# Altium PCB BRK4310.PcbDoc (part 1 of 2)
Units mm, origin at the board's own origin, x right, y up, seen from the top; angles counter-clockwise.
Board outline 150 x 90 mm, 2 copper layers (Top Layer, Bottom Layer), stack 1.646 mm thick; 21 components, 213 nets, 662 pads, 124 vias.
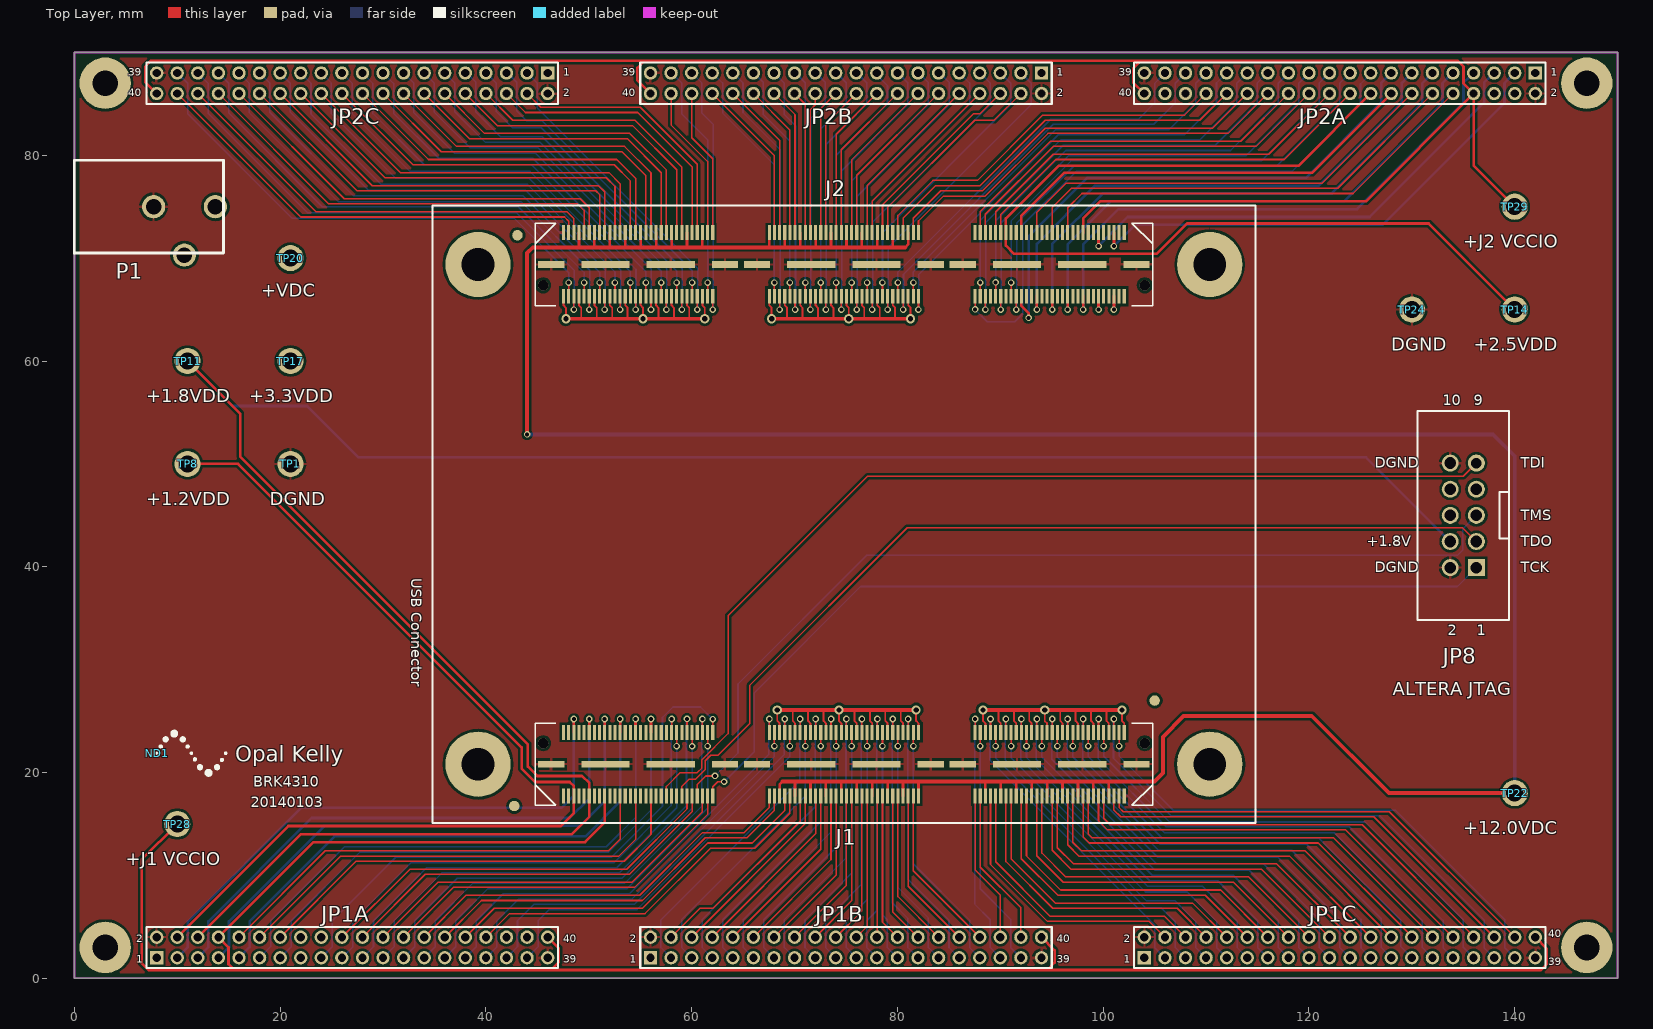
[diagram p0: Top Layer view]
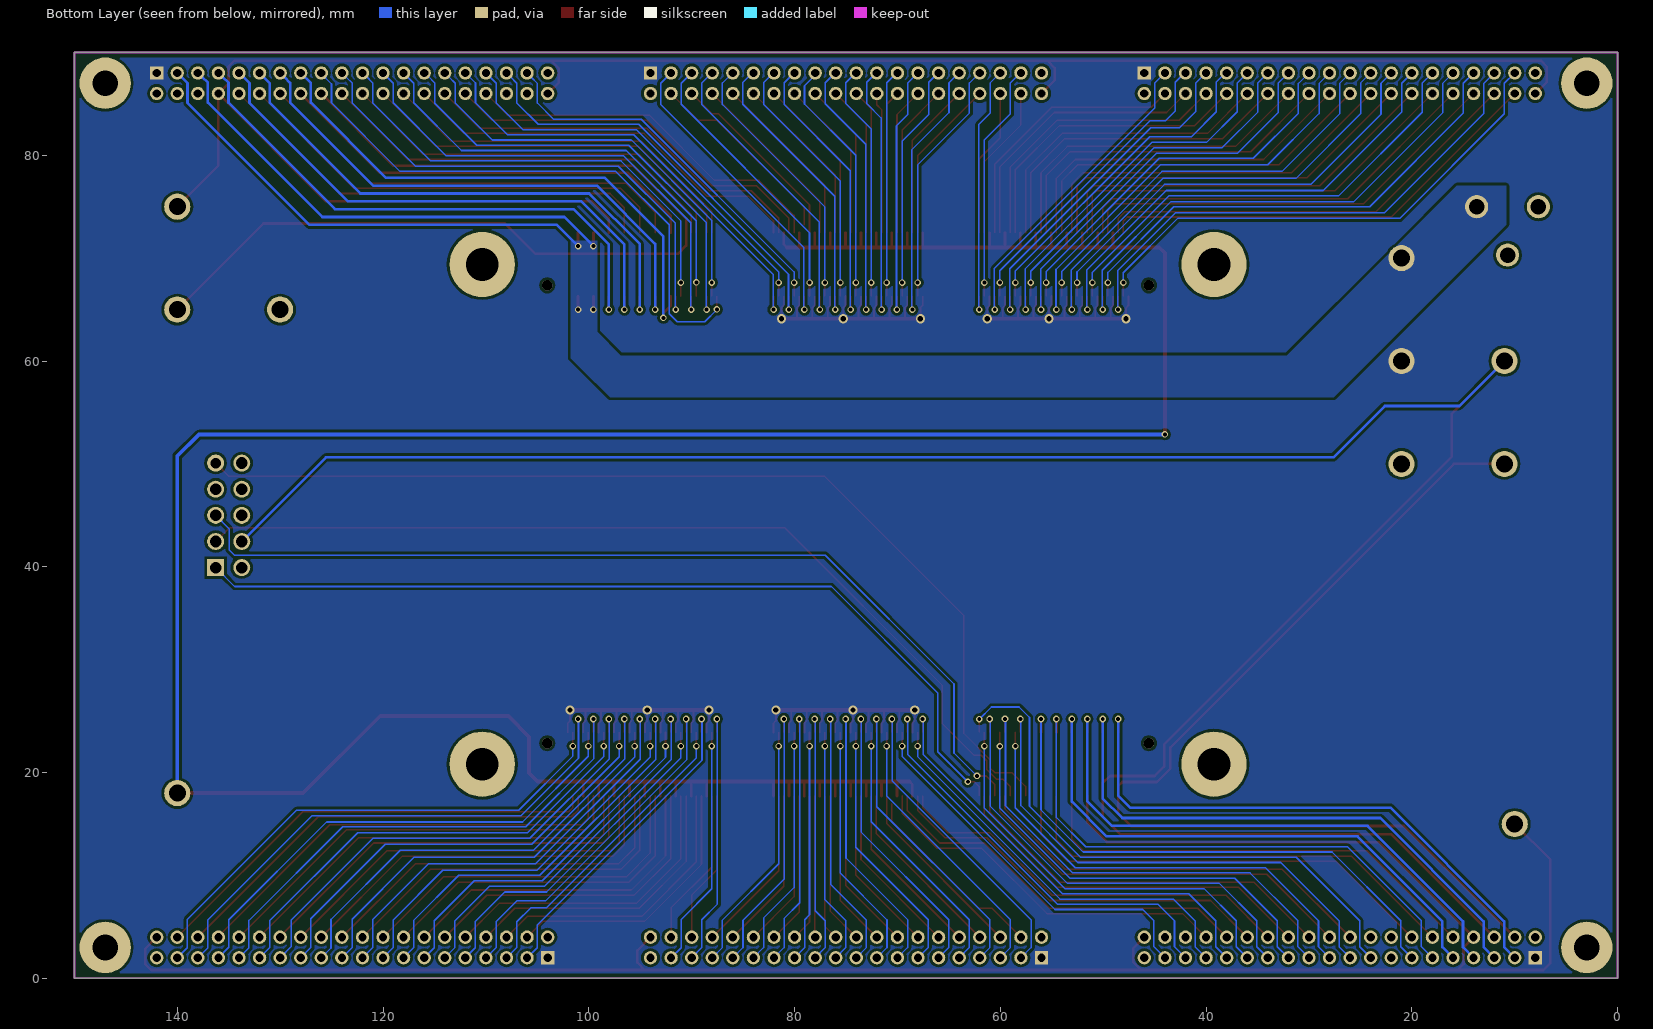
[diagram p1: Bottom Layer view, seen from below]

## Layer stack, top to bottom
Top Solder: solder mask 0.0102, Solder Resist, Dk 3.5
Top Layer: signal copper 0.0356
Dielectric1: core 1.5748, FR-4, Dk 4.8
Bottom Layer: signal copper 0.0356
Bottom Solder: solder mask 0.0102, Solder Resist, Dk 3.5

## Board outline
150,90 150,0 0,0 0,90

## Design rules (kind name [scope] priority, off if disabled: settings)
Clearance PolyClearance [InPolygon] p1: gap=0.254
Clearance [All] p2: gap=0.152
FabricationTestPointUsage TestPointUsage [All] p1: valid=0 allowmultiple=FALSE
FabricationTestpoint Testpoint [All] p1: side=3 testpointundercomponent=TRUE minsize=1.016 maxsize=2.54 preferedsize=1.524 minholesize=0 maxholesize=1.016 preferedholesize=0.813 testpointgrid=0.025 allowsidetop=TRUE allowsidebottom=TRUE usegrid=TRUE gridtolerance=0
HoleSize [All] p1: absolutevalues=TRUE maxlimit=6 minlimit=0.381 maxpercent=80.000 minpercent=20.000
PolygonConnect "Via Connect" [IsVia] p1: connectstyle=Direct reliefconductorwidth=0.254 reliefentries=4 polygonreliefangle="90 Angle" airgapwidth=0.254
PolygonConnect PolygonConnect_Top [OnLayer('Top Layer')] p2: connectstyle=Relief reliefconductorwidth=0.254 reliefentries=4 polygonreliefangle="90 Angle" airgapwidth=0.254
PolygonConnect PolygonConnect_Default [All] p3: connectstyle=Direct reliefconductorwidth=0.254 reliefentries=4 polygonreliefangle="90 Angle" airgapwidth=0.254
RoutingVias [All] p1: holewidth=0.381 width=0.635 viastyle="Through Hole" minholewidth=0.254 minwidth=0.508 maxholewidth=1.27 maxwidth=2.54
SilkToSolderMaskClearance SilkscreenOverComponentPads [IsPad] p1: minsilkscreentomaskgap=0.254 clearancetoexposedcopper=TRUE
SolderMaskExpansion [All] p1: expansion=0.102
Width [All] p1: maxlimit=1.016 minlimit=0.152 preferedwidth=0.152 minimp=50.000000 maximp=50.000000 favimp=50.000000
25 further rules are at their usual default settings.

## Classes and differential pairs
net class okPower: +1.2VDD +1.8VDD +2.5VDD +3.3VDD +12.0VDC +VCCIO2 +VCCIO3 +VCCIO4 +VCCIO5 +VCCIO6 +VDC +VREF_BANK2 +VREF_BANK3 +VREF_BANK4 +VREF_BANK5 +VREF_BANK6 +X_HSMC_VCCIO +Y_HSMC_VCCIO DGND
net class okJTAG: JTAG_TCK_1P8 JTAG_TDI_1P8 JTAG_TDO_1P8 JTAG_TMS_1P8

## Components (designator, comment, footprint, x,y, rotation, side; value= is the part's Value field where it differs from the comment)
J1 "QTH-090-01-F-D-A" QTH-090-01-X-D 74.795,20.815 r0 top locked
J2 "QTH-090-01-F-D-A" QTH-090-01-X-D 74.795,69.385 r180 top locked
JP1A "0877584016" HDR2X20-2MM 27,3 r0 top locked
JP1B "0877584016" HDR2X20-2MM 75,3 r0 top locked
JP1C "0877584016" HDR2X20-2MM 123,3 r0 top locked
JP2A "0877584016" HDR2X20-2MM 123,87 r180 top locked
JP2B "0877584016" HDR2X20-2MM 75,87 r180 top locked
JP2C "0877584016" HDR2X20-2MM 27,87 r180 top locked
JP8 "70246-1004" HDR2X5-SHRD 135,45 r90 top
ND1 "OKLOGO" oklogotiny 8.039,21.876 r0 top
P1 "PJ-102AH" CUI-PJ102A 0,75 r270 top
TP1 "DGND" TP_MED 21,50 r180 top
TP8 "+1.2VDD" TP_MED 11,50 r180 top
TP11 "+1.8VDD" TP_MED 11,60 r270 top
TP14 "+2.5VDD" TP_MED 140,65 r270 top
TP17 "+3.3VDD" TP_MED 21,60 r90 top
TP20 "+VDC" TP_MED 21,70 r180 top
TP22 "+12.0VDC" TP_MED 140,18 r270 top
TP24 "DGND" TP_MED 130,65 r270 top
TP28 "+J1 VCCIO" TP_MED 10,15 r270 top
TP29 "+J2 VCCIO" TP_MED 140,75 r270 top

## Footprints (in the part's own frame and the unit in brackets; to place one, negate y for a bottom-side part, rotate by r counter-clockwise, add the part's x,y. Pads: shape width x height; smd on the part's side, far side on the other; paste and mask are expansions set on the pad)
CUI-PJ102A [mm] "2.1mm/5.5mm DC power jack"
  round 2.25 hole 1.5: 1(0,13.7) 2(0,7.7) 3(4.7,10.7)
  silkscreen extent -4.5,0 4.5,14.5
HDR2X5-SHRD [mil] "0.1\" 2x5 shrouded header"
  rect 65x65 hole 44.88: 1(-200,-50)
  round 65 hole 44.88: 2(-200,50) 3(-100,-50) 4(-100,50) 5(0,-50) 6(0,50) 7(100,-50) 8(100,50) 10(200,50)
  round 65 hole 40: 9(200,-50)
  silkscreen extent -400,-175 400,175
HDR2X20-2MM [mm] "2mm 2x20 header"
  rect 1.3x1.3 hole 0.8: 1(-19,-1)
  round 1.3 hole 0.8: 2(-19,1) 3(-17,-1) 4(-17,1) 5(-15,-1) 6(-15,1) 7(-13,-1) 8(-13,1) 9(-11,-1) 10(-11,1) 11(-9,-1) 12(-9,1) 13(-7,-1) 14(-7,1) 15(-5,-1) 16(-5,1) 17(-3,-1) 18(-3,1) 19(-1,-1) 20(-1,1) 21(1,-1) 22(1,1) 23(3,-1) 24(3,1) 25(5,-1) 26(5,1) 27(7,-1) 28(7,1) 29(9,-1) 30(9,1) 31(11,-1) 32(11,1) 33(13,-1) 34(13,1) 35(15,-1) 36(15,1) 37(17,-1) 38(17,1) 39(19,-1) 40(19,1)
  silkscreen extent -20,-2 20,2
oklogotiny [mm] "Opal Kelly silkscreen logo (50 mil)."
  silkscreen extent -0.09,-2.1 6.75,2.1
QTH-090-01-X-D [mm]
  rect 2.54x0.64 smd: 0(-28.445,0) 0(-11.555,0) 0(-8.445,0) 0(8.445,0) 0(11.555,0) 0(28.445,0)
  rect 4.7x0.64 smd: 0(-23.175,0) 0(-16.825,0) 0(-3.175,0) 0(3.175,0) 0(16.825,0) 0(23.175,0)
  rect 0.3x1.45 smd: 1(-27.25,3.09) 2(-27.25,-3.09) 3(-26.75,3.09) 4(-26.75,-3.09) 5(-26.25,3.09) 6(-26.25,-3.09) 7(-25.75,3.09) 8(-25.75,-3.09) 9(-25.25,3.09) 10(-25.25,-3.09) 11(-24.75,3.09) 12(-24.75,-3.09) 13(-24.25,3.09) 14(-24.25,-3.09) 15(-23.75,3.09) 16(-23.75,-3.09) 17(-23.25,3.09) 18(-23.25,-3.09) 19(-22.75,3.09) 20(-22.75,-3.09) 21(-22.25,3.09) 22(-22.25,-3.09) 23(-21.75,3.09) 24(-21.75,-3.09) 25(-21.25,3.09) 26(-21.25,-3.09) 27(-20.75,3.09) 28(-20.75,-3.09) 29(-20.25,3.09) 30(-20.25,-3.09) 31(-19.75,3.09) 32(-19.75,-3.09) 33(-19.25,3.09) 34(-19.25,-3.09) 35(-18.75,3.09) 36(-18.75,-3.09) 37(-18.25,3.09) 38(-18.25,-3.09) 39(-17.75,3.09) 40(-17.75,-3.09) 41(-17.25,3.09) 42(-17.25,-3.09) 43(-16.75,3.09) 44(-16.75,-3.09) 45(-16.25,3.09) 46(-16.25,-3.09) 47(-15.75,3.09) 48(-15.75,-3.09) 49(-15.25,3.09) 50(-15.25,-3.09) 51(-14.75,3.09) 52(-14.75,-3.09) 53(-14.25,3.09) 54(-14.25,-3.09) 55(-13.75,3.09) 56(-13.75,-3.09) 57(-13.25,3.09) 58(-13.25,-3.09) 59(-12.75,3.09) 60(-12.75,-3.09) 61(-7.25,3.09) 62(-7.25,-3.09) 63(-6.75,3.09) 64(-6.75,-3.09) 65(-6.25,3.09) 66(-6.25,-3.09) 67(-5.75,3.09) 68(-5.75,-3.09) 69(-5.25,3.09) 70(-5.25,-3.09) 71(-4.75,3.09) 72(-4.75,-3.09) 73(-4.25,3.09) 74(-4.25,-3.09) 75(-3.75,3.09) 76(-3.75,-3.09) 77(-3.25,3.09) 78(-3.25,-3.09) 79(-2.75,3.09) 80(-2.75,-3.09) 81(-2.25,3.09) 82(-2.25,-3.09) 83(-1.75,3.09) 84(-1.75,-3.09) 85(-1.25,3.09) 86(-1.25,-3.09) 87(-0.75,3.09) 88(-0.75,-3.09) 89(-0.25,3.09) 90(-0.25,-3.09) 91(0.25,3.09) 92(0.25,-3.09) 93(0.75,3.09) 94(0.75,-3.09) 95(1.25,3.09) 96(1.25,-3.09) 97(1.75,3.09) 98(1.75,-3.09) 99(2.25,3.09) 100(2.25,-3.09) 101(2.75,3.09) 102(2.75,-3.09) 103(3.25,3.09) 104(3.25,-3.09) 105(3.75,3.09) 106(3.75,-3.09) 107(4.25,3.09) 108(4.25,-3.09) 109(4.75,3.09) 110(4.75,-3.09) 111(5.25,3.09) 112(5.25,-3.09) 113(5.75,3.09) 114(5.75,-3.09) 115(6.25,3.09) 116(6.25,-3.09) 117(6.75,3.09) 118(6.75,-3.09) 119(7.25,3.09) 120(7.25,-3.09) 121(12.75,3.09) 122(12.75,-3.09) 123(13.25,3.09) 124(13.25,-3.09) 125(13.75,3.09) 126(13.75,-3.09) 127(14.25,3.09) 128(14.25,-3.09) 129(14.75,3.09) 130(14.75,-3.09) 131(15.25,3.09) 132(15.25,-3.09) 133(15.75,3.09) 134(15.75,-3.09) 135(16.25,3.09) 136(16.25,-3.09) 137(16.75,3.09) 138(16.75,-3.09) 139(17.25,3.09) 140(17.25,-3.09) 141(17.75,3.09) 142(17.75,-3.09) 143(18.25,3.09) 144(18.25,-3.09) 145(18.75,3.09) 146(18.75,-3.09) 147(19.25,3.09) 148(19.25,-3.09) 149(19.75,3.09) 150(19.75,-3.09) 151(20.25,3.09) 152(20.25,-3.09) 153(20.75,3.09) 154(20.75,-3.09) 155(21.25,3.09) 156(21.25,-3.09) 157(21.75,3.09) 158(21.75,-3.09) 159(22.25,3.09) 160(22.25,-3.09) 161(22.75,3.09) 162(22.75,-3.09) 163(23.25,3.09) 164(23.25,-3.09) 165(23.75,3.09) 166(23.75,-3.09) 167(24.25,3.09) 168(24.25,-3.09) 169(24.75,3.09) 170(24.75,-3.09) 171(25.25,3.09) 172(25.25,-3.09) 173(25.75,3.09) 174(25.75,-3.09) 175(26.25,3.09) 176(26.25,-3.09) 177(26.75,3.09) 178(26.75,-3.09) 179(27.25,3.09) 180(27.25,-3.09)
  round 1.02 hole 1.02 unplated: MH(-29.24,2.03) MH(29.24,2.03)
  silkscreen extent -30,-4 30,4
TP_MED [mil] "Testpoint - medium sized"
  round 100 hole 65: 1(0,0)

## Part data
J1 J2: library part 000876, "0.5mm hi-speed, high-density header (Female)"
JP1A JP1B JP1C JP2A JP2B JP2C: library part 000583, "2mm header, 20x2, thru-hole"
JP8: library part 000777, "2.54mm, 10 Pos, Dual Row Header"
ND1: "Opal Kelly PCB Logo"
P1: library part 000356, "DC power connector - high current"
TP1 TP8 TP11 TP14 TP17 TP20 TP22 TP24 TP28 TP29: library part 000812, "Testpoint."

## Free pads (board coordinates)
  round 1.016 smd mask+0.508: FD2(43.066,72.22) FD2(105,27) FD3(42.75,16.75)
  round 5 hole 2.5: MH(3,3) MH(3,87) MH(147,3) MH(147,87)
  round 6.35 hole 3.175: MH2(39.235,69.385) MH3(39.235,20.815) MH4(110.355,69.385) MH5(110.355,20.815)

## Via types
v1: diameter 0.635, hole 0.381, Top Layer to Bottom Layer, tented both sides, 112 vias
v2: diameter 0.889, hole 0.508, Top Layer to Bottom Layer, tented both sides, 12 vias

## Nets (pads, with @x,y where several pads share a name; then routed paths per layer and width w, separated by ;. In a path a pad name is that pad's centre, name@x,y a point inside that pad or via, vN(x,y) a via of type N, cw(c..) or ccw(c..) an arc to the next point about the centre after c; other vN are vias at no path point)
+1.2VDD: J1.6 JP1A.4 TP8.1 | length 98
  Top Layer w0.254: JP1A.4@9.59,4.2 JP1A.4@9.695,4.305 ; JP1A.4@10,4 20.805,14.805 47.291,14.805 48.545,16.059 J1.6@48.545,17.725 48.545,18.684 48.146,19.083 44.793,19.083 43.472,20.404 43.472,22.436 15.908,50 TP8.1@11,50
+1.8VDD: J1.12 JP1A.6 JP8.4 TP11.1 | length 235.9
  Top Layer w0.254: TP11.1@11,60 16.129,54.871 16.129,50.694 44.082,22.741 44.082,20.582 44.996,19.667 49.34,19.667 50.045,18.962 J1.12@50.045,17.725 50.045,15.705 48.358,14.018 22.018,14.018 JP1A.6@12,4
  Bottom Layer w0.254: TP11.1@11,60 15.374,55.626 22.631,55.626 27.627,50.63 125.56,50.63 JP8.4@133.73,42.46
+2.5VDD: J2.48 JP2A.18 TP14.1 | length 97.6
  Top Layer w0.254: JP2A.18@126,86 118.976,78.976 95.669,78.976 90.545,73.852 J2.48@90.545,72.475 90.545,71.223 91.351,70.417 105.194,70.417 108.141,73.363 131.637,73.363 TP14.1@140,65
+3.3VDD: J1.65 J1.71 J1.77 J1.83 J1.89 J1.95 J1.101 J1.107 J1.113 J1.119 J1.125 J1.131 J1.137 J1.143 J1.149 J1.155 J1.161 J1.167 J1.173 J1.179 J2.65 J2.71 J2.77 J2.83 J2.89 J2.95 J2.101 J2.107 J2.113 J2.119 J2.125 J2.131 J2.137 J2.143 J2.149 J2.155 J2.161 J2.167 J2.173 J2.179 JP1A.1 JP1B.1 JP1C.1 JP2A.1 JP2B.1 JP2C.1 TP17.1 | length 145.3
  Top Layer w0.178: J2.179@47.545,66.295 47.545,65.401 47.772,65.173 v2(47.772,64.106) ; J2.173@49.045,66.295 49.045,65.401 49.272,65.173 49.272,64.106 ; J2.167@50.545,66.295 50.545,65.401 50.772,65.173 50.772,64.106 ; J2.161@52.045,66.295 52.045,65.401 52.272,65.173 52.272,64.106 ; J2.155@53.545,66.295 53.545,65.401 53.772,65.173 53.772,64.106 ; J2.149@55.038,66.316 55.038,65.422 55.266,65.194 v2@55.266,64.128 ; J2.143@56.545,66.295 56.545,65.401 56.772,65.173 56.772,64.106 ; J2.137@58.045,66.295 58.045,65.401 58.272,65.173 58.272,64.106 ; J2.131@59.545,66.295 59.545,65.401 59.772,65.173 59.772,64.106 ; J2.125@61.045,66.295 61.045,65.401 61.272,65.173 v2(61.272,64.106) ; J2.119@67.545,66.295 67.545,65.401 67.772,65.173 v2(67.772,64.106) ; v2(68.318,26.094) 68.318,25.027 68.545,24.799 J1.65@68.545,23.905 ; J2.113@69.045,66.295 69.045,65.401 69.272,65.173 69.272,64.106 ; 69.818,26.094 69.818,25.027 70.045,24.799 J1.71@70.045,23.905 ; J2.107@70.545,66.295 70.545,65.401 70.772,65.173 70.772,64.106 ; 71.318,26.094 71.318,25.027 71.545,24.799 J1.77@71.545,23.905 ; J2.101@72.045,66.295 72.045,65.401 72.272,65.173 72.272,64.106 ; 72.818,26.094 72.818,25.027 73.045,24.799 J1.83@73.045,23.905 ; J2.95@73.545,66.295 73.545,65.401 73.772,65.173 73.772,64.106 ; v2@74.324,26.072 74.324,25.006 74.552,24.778 J1.89@74.552,23.884 ; J2.89@75.038,66.316 75.038,65.422 75.266,65.194 v2@75.266,64.128 ; 75.818,26.094 75.818,25.027 76.045,24.799 J1.95@76.045,23.905 ; J2.83@76.545,66.295 76.545,65.401 76.772,65.173 76.772,64.106 ; 77.318,26.094 77.318,25.027 77.545,24.799 J1.101@77.545,23.905 ; J2.77@78.045,66.295 78.045,65.401 78.272,65.173 78.272,64.106 ; 78.818,26.094 78.818,25.027 79.045,24.799 J1.107@79.045,23.905 ; J2.71@79.545,66.295 79.545,65.401 79.772,65.173 79.772,64.106 ; 80.318,26.094 80.318,25.027 80.545,24.799 J1.113@80.545,23.905 ; J2.65@81.045,66.295 81.045,65.401 81.272,65.173 v2(81.272,64.106) ; v2(81.818,26.094) 81.818,25.027 82.045,24.799 J1.119@82.045,23.905 ; v2(88.318,26.094) 88.318,25.027 88.545,24.799 J1.125@88.545,23.905 ; 89.818,26.094 89.818,25.027 90.045,24.799 J1.131@90.045,23.905 ; 91.318,26.094 91.318,25.027 91.545,24.799 J1.137@91.545,23.905 ; 92.818,26.094 92.818,25.027 93.045,24.799 J1.143@93.045,23.905 ; v2@94.324,26.072 94.324,25.006 94.552,24.778 J1.149@94.552,23.884 ; 95.818,26.094 95.818,25.027 96.045,24.799 J1.155@96.045,23.905 ; 97.318,26.094 97.318,25.027 97.545,24.799 J1.161@97.545,23.905 ; 98.818,26.094 98.818,25.027 99.045,24.799 J1.167@99.045,23.905 ; 100.318,26.094 100.318,25.027 100.545,24.799 J1.173@100.545,23.905 ; v2(101.818,26.094) 101.818,25.027 102.045,24.799 J1.179@102.045,23.905
  Top Layer w0.381: v2(47.772,64.106) 49.272,64.106 50.772,64.106 52.272,64.106 53.772,64.106 56.772,64.106 58.272,64.106 59.772,64.106 v2(61.272,64.106) ; v2(67.772,64.106) 69.272,64.106 70.772,64.106 72.272,64.106 73.772,64.106 76.772,64.106 78.272,64.106 79.772,64.106 v2(81.272,64.106) ; v2(68.318,26.094) 69.818,26.094 71.318,26.094 72.818,26.094 75.818,26.094 77.318,26.094 78.818,26.094 80.318,26.094 v2(81.818,26.094) ; v2(88.318,26.094) 89.818,26.094 91.318,26.094 92.818,26.094 95.818,26.094 97.318,26.094 98.818,26.094 100.318,26.094 v2(101.818,26.094)
  other v2: 74.318,26.094 94.318,26.094 55.272,64.106 75.272,64.106
+12.0VDC: J1.66 J1.72 J1.78 J1.84 J1.90 J1.96 J1.102 J1.108 J1.114 J1.120 J1.126 J1.132 J1.138 J1.144 J1.150 J1.156 J1.162 J1.168 J1.174 J2.66 J2.72 J2.78 J2.84 J2.90 J2.96 J2.102 J2.108 J2.114 J2.120 J2.126 J2.132 J2.138 J2.144 J2.150 J2.156 J2.162 J2.168 J2.174 TP22.1 | length 317.5
  Top Layer w0.254: 49.045,71.092 J2.174@49.045,72.475 ; 50.545,71.091 J2.168@50.545,72.475 ; 52.045,71.064 J2.162@52.045,72.475 ; 53.545,71.063 J2.156@53.545,72.475 ; 55.045,71.067 J2.150@55.045,72.475 ; 56.545,71.085 J2.144@56.545,72.475 ; 58.045,71.059 J2.138@58.045,72.475 ; 59.545,71.057 J2.132@59.545,72.475 ; 61.045,71.056 J2.126@61.045,72.475 ; 67.545,71.058 J2.120@67.545,72.475 ; J1.66@68.545,17.725 68.545,18.863 68.83,19.148 ; 69.045,71.082 J2.114@69.045,72.475 ; J1.72@70.045,17.725 70.045,19.144 ; 70.545,71.055 J2.108@70.545,72.475 ; J1.78@71.545,17.725 71.545,19.126 ; 72.045,71.079 J2.102@72.045,72.475 ; J1.84@73.045,17.725 73.045,19.147 ; 73.545,71.078 J2.96@73.545,72.475 ; J1.90@74.545,17.725 74.545,19.098 ; 75.045,71.102 J2.90@75.045,72.475 ; J1.96@76.045,17.725 76.045,19.122 ; 76.545,71.053 J2.84@76.545,72.475 ; J1.102@77.545,17.725 77.545,19.121 ; 78.045,71.074 J2.78@78.045,72.475 ; J1.108@79.045,17.725 79.045,19.145 ; 79.545,71.056 J2.72@79.545,72.475 ; J1.114@80.545,17.725 80.545,19.118 ; 80.76,71.052 81.045,71.337 J2.66@81.045,72.475 ; J1.120@82.045,17.725 82.045,19.142 ; J1.126@88.545,17.725 88.545,19.144 ; J1.132@90.045,17.725 90.045,19.143 ; J1.138@91.545,17.725 91.545,19.141 ; J1.144@93.045,17.725 93.045,19.115 ; J1.150@94.545,17.725 94.545,19.133 ; J1.156@96.045,17.725 96.045,19.137 ; J1.162@97.545,17.725 97.545,19.136 ; J1.168@99.045,17.725 99.045,19.109 ; J1.174@100.545,17.725 100.545,19.108
  Top Layer w0.381: v1(44,52.871) 44,70.5 44.552,71.052 49.086,71.052 ; 49.045,71.092 49.086,71.052 ; 50.545,71.091 50.584,71.052 ; 53.545,71.063 53.556,71.052 ; 61.045,71.056 61.049,71.052 ; 67.545,71.058 67.552,71.052 ; 68.83,19.148 70.05,19.148 ; 69.045,71.082 69.076,71.052 ; 70.045,19.144 70.05,19.148 ; 70.545,71.055 70.549,71.052 ; 71.545,19.126 71.523,19.148 ; 72.045,71.079 72.073,71.052 ; 73.045,19.147 73.047,19.148 ; 74.545,19.098 74.495,19.148 ; 75.045,71.102 75.095,71.052 ; 76.545,71.053 76.543,71.052 ; 77.545,19.121 77.517,19.148 ; 78.045,71.074 78.067,71.052 ; 79.045,19.145 79.041,19.148 ; 79.545,71.056 79.54,71.052 ; 80.545,19.118 80.514,19.148 ; 80.76,71.052 79.54,71.052 ; 82.045,19.142 82.038,19.148 ; 88.545,19.144 88.541,19.148 ; 96.045,19.137 96.034,19.148 ; 99.045,19.109 99.006,19.148 ; 100.53,19.123 100.545,19.108 ; TP22.1@140,18 127.771,18 120.269,25.502 107.823,25.502 105.795,23.474 105.795,19.943 105,19.148 99.006,19.148 ; 49.086,71.052 50.584,71.052 ; 50.584,71.052 53.556,71.052 ; 53.556,71.052 61.049,71.052 ; 61.049,71.052 67.552,71.052 ; 67.552,71.052 69.076,71.052 ; 69.076,71.052 70.549,71.052 ; 70.05,19.148 71.523,19.148 ; 70.549,71.052 72.073,71.052 ; 71.523,19.148 73.047,19.148 ; 72.073,71.052 75.095,71.052 ; 73.047,19.148 74.495,19.148 ; 74.495,19.148 77.517,19.148 ; 75.095,71.052 76.543,71.052 ; 76.543,71.052 78.067,71.052 ; 77.517,19.148 79.041,19.148 ; 78.067,71.052 79.54,71.052 ; 79.041,19.148 80.514,19.148 ; 80.514,19.148 82.038,19.148 ; 82.038,19.148 88.541,19.148 ; 88.541,19.148 96.034,19.148 ; 96.034,19.148 99.006,19.148
  Bottom Layer w0.381: v1(44,52.871) 137.886,52.871 140,50.757 TP22.1@140,18
+VCCIO2: J1.5 JP1A.3 | length 55.3
  Top Layer w0.254: J1.5@48.545,23.905 v1(48.545,25.206)
  Bottom Layer w0.254: JP1A.3@10,2 11.031,3.031 11.031,5.545 22.08,16.594 47.384,16.594 48.545,17.755 v1(48.545,25.206)
+VCCIO3: J1.11 JP1A.5 | length 55
  Top Layer w0.254: J1.11@50.045,23.905 v1(50.045,25.206)
  Bottom Layer w0.254: JP1A.5@12,2 13.031,3.031 13.031,5.545 23.064,15.578 48.146,15.578 50.045,17.477 v1(50.045,25.206)
+VCCIO4: J2.17 JP2A.7 | length 53.6
  Top Layer w0.254: v1(98.045,64.994) J2.17@98.045,66.295
  Bottom Layer w0.254: v1(98.045,64.994) 98.045,71.319 101.486,74.76 124.664,74.76 135.014,85.11 135.014,87.054 135.59,87.63 JP2A.7@135.59,88.2
+VCCIO5: J2.23 JP2A.9 | length 53.2
  Top Layer w0.254: v1(96.545,64.994) J2.23@96.545,66.295
  Bottom Layer w0.254: v1(96.545,64.994) 96.545,71.343 100.724,75.522 123.426,75.522 132.982,85.078 132.982,87.028 133.59,87.636 JP2A.9@133.59,88.2
+VCCIO6: J2.29 JP2A.11 | length 52.6
  Top Layer w0.254: v1@95.045,65.017 J2.29@95.045,66.295
  Bottom Layer w0.254: v1(95.045,64.994) 95.045,71.367 99.962,76.284 122.197,76.284 131.001,85.088 131.001,86.977 131.59,87.567 JP2A.11@131.59,88.2
+VDC: J2.5 J2.6 J2.11 J2.12 JP2A.3 JP2A.5 P1.1 TP20.1 | length 98.8
  Top Layer w0.254: v1(99.545,64.994) J2.11@99.545,66.295 ; v1(99.545,71.174) J2.12@99.545,72.475 ; v1(101.045,64.994) J2.5@101.045,66.295 ; v1(101.045,71.174) J2.6@101.045,72.475
  Bottom Layer w0.254: v1(99.545,71.174) 102.369,73.998 125.902,73.998 137.021,85.117 137.021,87.054 137.59,87.623 JP2A.5@137.59,88.2 ; v1(101.045,71.174) 103.107,73.236 127.14,73.236 139.002,85.098 139.002,87.002 139.59,87.59 JP2A.3@139.59,88.2
+VREF_BANK2: J1.17 JP1A.7 | length 54.6
  Top Layer w0.254: J1.17@51.545,23.905 v1(51.545,25.206)
  Bottom Layer w0.254: JP1A.7@14,2 15.031,3.031 15.031,5.545 24.302,14.816 49.162,14.816 51.545,17.199 v1(51.545,25.206)
+VREF_BANK3: J1.23 JP1A.9 | length 54.1
  Top Layer w0.254: J1.23@53.045,23.905 v1(53.045,25.206)
  Bottom Layer w0.254: JP1A.9@16,2 17.031,3.031 17.031,5.545 25.286,13.8 49.67,13.8 53.045,17.175 v1(53.045,25.206)
+VREF_BANK4: J2.35 JP2A.13 | length 52.1
  Top Layer w0.254: v1@93.545,65.041 J2.35@93.545,66.295
  Bottom Layer w0.254: v1(93.545,64.994) 93.545,71.391 99.2,77.046 120.959,77.046 129.02,85.106 129.02,87.028 129.59,87.599 JP2A.13@129.59,88.2
+VREF_BANK5: J2.41 JP2A.15 | length 53.3
  Top Layer w0.254: J2.41@92.045,66.295 92.045,65.354 92.748,64.651 v1(92.748,64.194) v1@92.774,64.168
  Bottom Layer w0.254: v1(92.748,64.194) 92.748,72.118 98.438,77.808 119.698,77.808 127.013,85.123 127.013,87.013 JP2A.15@128,88
+VREF_BANK6: J2.42 JP2A.16 | length 42.5
  Top Layer w0.254: J2.42@92.045,72.475 92.045,74.133 96.203,78.291 120.291,78.291 JP2A.16@128,86
+X_HSMC_VCCIO: J1.18 JP1A.8 JP1A.40 JP1B.40 JP1C.40 TP28.1 | length 211.7
  Top Layer w0.254: TP28.1@10,15 6.541,11.541 6.541,1.481 7.209,0.813 15.545,0.813 ; JP1A.40@46,4 47.092,2.908 47.092,1.575 46.33,0.813 ; J1.18@51.545,17.725 51.545,15.122 49.653,13.23 23.23,13.23 JP1A.8@14,4 14.986,3.014 14.986,1.372 15.545,0.813 ; JP1B.40@94,4 95.275,2.725 95.275,1.524 94.564,0.813 ; JP1C.40@142,4 143.129,2.871 143.129,1.397 142.545,0.813 94.564,0.813 ; 15.545,0.813 46.33,0.813 ; 46.33,0.813 94.564,0.813
+Y_HSMC_VCCIO: J2.18 JP2A.8 JP2A.40 JP2B.40 JP2C.40 TP29.1 | length 199.7
  Top Layer w0.254: JP2C.40@8,86 6.871,87.129 6.871,88.603 7.455,89.187 55.436,89.187 ; JP2B.40@56,86 54.725,87.275 54.725,88.476 55.436,89.187 ; J2.18@98.045,72.475 98.045,73.859 99.708,75.522 125.522,75.522 JP2A.8@136,86 ; JP2A.40@104,86 102.908,87.092 102.908,88.425 103.67,89.187 ; TP29.1@140,75 136,79 JP2A.8@136,86 ; 55.436,89.187 103.67,89.187 ; 103.67,89.187 134.455,89.187 135.014,88.628 135.014,86.986 JP2A.8@136,86
BANK1_CLK: J1.29 JP1A.11 | length 54.5
  Top Layer w0.254: J1.29@54.545,23.905 v1@54.545,25.183
  Bottom Layer w0.152: JP1A.11@18,2 19.073,3.073 19.073,5.596 26.261,12.784 51.702,12.784 54.545,15.627 v1(54.545,25.206)
BANK8_CLK: J1.35 JP1A.13 | length 53.6
  Top Layer w0.254: J1.35@56.045,23.905 v1@56.045,25.159
  Bottom Layer w0.152: JP1A.13@20,2 21.073,3.073 21.073,5.596 27.753,12.276 51.956,12.276 56.045,16.365 v1(56.045,25.206)
C_DET: J2.59 JP2A.17 | length 56.5
  Top Layer w0.152: v1(87.545,65.01) J2.59@87.545,66.295
  Bottom Layer w0.152: v1(87.545,65.01) 88.728,63.827 91.411,63.827 92.19,64.606 92.19,73.242 97.38,78.432 118.345,78.432 125.006,85.093 125.006,86.927 125.59,87.51 JP2A.17@125.59,88.2
DGND: J1.0 J1.180 J2.0 J2.180 JP1A.2 JP1A.39 JP1B.2 JP1B.39 JP1C.2 JP1C.39 JP2A.2 JP2A.39 JP2B.2 JP2B.39 JP2C.2 JP2C.39 JP8.2 JP8.10 P1.2 TP1.1 TP24.1
J1_49: J1.49 JP1A.23 | length 46.8
  Top Layer w0.152: J1.49@59.545,23.905 v1(59.545,25.208)
  Bottom Layer w0.152: JP1A.23@30,2 31.073,3.073 31.073,5.596 35.721,10.244 52.972,10.244 59.499,16.771 v1@59.499,25.142
J1_50: J1.50 JP1A.20 | length 40
  Top Layer w0.152: JP1A.20@26,4 32.614,10.614 53.692,10.614 59.545,16.467 J1.50@59.545,17.725
J1_51: J1.51 JP1A.25 | length 42.9
  Top Layer w0.152: v1(60.045,22.555) J1.51@60.045,23.905
  Bottom Layer w0.152: JP1A.25@32,2 33.073,3.073 33.073,5.596 37.213,9.736 53.226,9.736 60.045,16.555 v1(60.045,22.555)
J1_52: J1.52 JP1A.22 | length 38.6
  Top Layer w0.152: JP1A.22@28,4 34.106,10.106 53.946,10.106 60.045,16.205 J1.52@60.045,17.725
J1_55: J1.55 JP1A.27 | length 44.3
  Top Layer w0.152: J1.55@61.045,23.905 v1(61.045,25.206)
  Bottom Layer w0.152: JP1A.27@34,2 35.073,3.073 35.073,5.596 38.705,9.228 53.48,9.228 60.999,16.747 v1@60.999,25.16
J1_56: J1.56 JP1A.24 | length 37.6
  Top Layer w0.152: JP1A.24@30,4 35.344,9.344 54.2,9.344 61.045,16.189 J1.56@61.045,17.725
J1_57: J1.57 JP1A.29 | length 40.4
  Top Layer w0.152: v1(61.545,22.573) J1.57@61.545,23.905
  Bottom Layer w0.152: JP1A.29@36,2 37.073,3.073 37.073,5.596 40.197,8.72 53.734,8.72 61.545,16.531 v1(61.545,22.573)
J1_58: J1.58 JP1A.26 | length 36.3
  Top Layer w0.152: JP1A.26@32,4 36.836,8.836 54.454,8.836 61.545,15.927 J1.58@61.545,17.725
J1_61: J1.61 JP1A.31 | length 43.9
  Top Layer w0.152: J1.61@67.545,23.905 v1(67.545,25.206)
  Bottom Layer w0.152: JP1A.31@38,2 39.073,3.073 39.073,5.596 41.689,8.212 53.95,8.212 67.499,21.761 v1@67.499,25.16
J1_62: J1.62 JP1A.28 | length 39.9
  Top Layer w0.152: JP1A.28@34,4 38.074,8.074 54.962,8.074 61.058,14.17 65.122,14.17 67.545,16.593 J1.62@67.545,17.725
J1_63: J1.63 JP1A.33 | length 40
  Top Layer w0.152: v1(68.045,22.573) J1.63@68.045,23.905
  Bottom Layer w0.152: JP1A.33@40,2 41.073,3.073 41.073,5.596 43.181,7.704 54.2,7.704 68.045,21.549 v1(68.045,22.573)
J1_64: J1.64 JP1A.30 | length 38.5
  Top Layer w0.152: JP1A.30@36,4 39.566,7.566 55.216,7.566 61.312,13.662 65.376,13.662 68.045,16.331 J1.64@68.045,17.725
J1_67: J1.67 JP1A.35 | length 41.4
  Top Layer w0.152: J1.67@69.045,23.905 v1(69.045,25.206)
  Bottom Layer w0.152: JP1A.35@42,2 43.073,3.073 43.073,5.596 44.673,7.196 54.434,7.196 68.999,21.761 v1@68.999,25.16
J1_68: J1.68 JP1A.32 | length 37.6
  Top Layer w0.152: JP1A.32@38,4 40.804,6.804 55.216,6.804 61.566,13.154 65.884,13.154 69.045,16.315 J1.68@69.045,17.725
J1_69: J1.69 JP1A.37 | length 37.5
  Top Layer w0.152: v1(69.545,22.573) J1.69@69.545,23.905
  Bottom Layer w0.152: JP1A.37@44,2 45.073,3.073 45.073,5.596 46.165,6.688 54.684,6.688 69.545,21.549 v1(69.545,22.573)
J1_70: J1.70 JP1A.34 | length 36.2
  Top Layer w0.152: JP1A.34@40,4 42.296,6.296 55.47,6.296 61.82,12.646 66.138,12.646 69.545,16.053 J1.70@69.545,17.725
J1_73: J1.73 JP1B.3 | length 30.5
  Top Layer w0.152: J1.73@70.545,23.905 v1(70.545,25.206)
  Bottom Layer w0.152: JP1B.3@58,2 57.015,2.985 57.015,5.697 70.499,19.182 v1@70.499,25.16
J1_74: J1.74 JP1B.4 | length 18.9
  Top Layer w0.152: JP1B.4@58,4 60.804,6.804 62.074,6.804 70.545,15.275 70.545,16.964
J1_75: J1.75 JP1B.5 | length 27.3
  Top Layer w0.152: v1(71.045,22.573) J1.75@71.045,23.905
  Bottom Layer w0.152: JP1B.5@60,2 59.015,2.985 59.015,5.697 71.045,17.728 v1(71.045,22.573)
J1_76: J1.76 JP1B.6 | length 18.3
  Top Layer w0.152: JP1B.6@60,4 71.013,15.013 71.045,15.013 J1.76@71.045,17.725
J1_79: J1.79 JP1B.7 | length 29.4
  Top Layer w0.152: J1.79@72.045,23.905 v1(72.045,25.206)
  Bottom Layer w0.152: JP1B.7@62,2 61.015,2.985 61.015,5.697 71.999,16.682 v1@71.999,25.16
J1_80: J1.80 JP1B.8 | length 17.9
  Top Layer w0.152: JP1B.8@62,4 72.045,14.045 J1.80@72.045,17.725
J1_81: J1.81 JP1B.9 | length 26.3
  Top Layer w0.152: v1(72.545,22.573) J1.81@72.545,23.905
  Bottom Layer w0.152: JP1B.9@64,2 63.015,2.985 63.015,5.697 72.545,15.228 v1(72.545,22.573)
J1_82: J1.82 JP1B.10 | length 17.3
  Top Layer w0.152: JP1B.10@64,4 72.545,12.545 J1.82@72.545,17.725
J1_85: J1.85 JP1B.11 | length 28.4
  Top Layer w0.152: J1.85@73.545,23.905 v1(73.545,25.206)
  Bottom Layer w0.152: JP1B.11@66,2 65.015,2.985 65.015,5.697 73.499,14.182 v1@73.499,25.16
J1_86: J1.86 JP1B.12 | length 16.9
  Top Layer w0.152: JP1B.12@66,4 73.545,11.545 J1.86@73.545,17.725
J1_87: J1.87 JP1B.13 | length 25.2
  Top Layer w0.152: v1(74.045,22.573) J1.87@74.045,23.905
  Bottom Layer w0.152: JP1B.13@68,2 67.015,2.985 67.015,5.697 74.045,12.728 v1(74.045,22.573)
J1_88: J1.88 JP1B.14 | length 16.2
  Top Layer w0.152: JP1B.14@68,4 74.045,10.045 J1.88@74.045,17.725
J1_91: J1.91 JP1B.15 | length 27.3
  Top Layer w0.152: J1.91@75.045,23.905 v1(75.045,25.206)
  Bottom Layer w0.152: JP1B.15@70,2 69.015,2.985 69.015,5.713 74.999,11.697 v1@74.999,25.16
J1_92: J1.92 JP1B.16 | length 15.8
  Top Layer w0.152: JP1B.16@70,4 75.045,9.045 J1.92@75.045,17.725
J1_93: J1.93 JP1B.17 | length 24.2
  Top Layer w0.152: v1(75.545,22.573) J1.93@75.545,23.905
  Bottom Layer w0.152: JP1B.17@72,2 71.015,2.985 71.015,5.681 75.545,10.211 v1(75.545,22.573)
J1_94: J1.94 JP1B.18 | length 15.2
  Top Layer w0.152: JP1B.18@72,4 75.545,7.545 J1.94@75.545,17.725
J1_97: J1.97 JP1B.19 | length 26.3
  Top Layer w0.152: J1.97@76.545,23.905 v1(76.545,25.206)
  Bottom Layer w0.152: JP1B.19@74,2 73.015,2.985 73.015,5.649 76.499,9.133 v1@76.499,25.16
J1_98: J1.98 JP1B.20 | length 14.8
  Top Layer w0.152: JP1B.20@74,4 76.545,6.545 76.545,7.399 ; 76.52,7.374 76.545,7.399 ; J1.98@76.545,17.725 76.545,7.399
J1_99: J1.99 JP1B.21 | length 23.2
  Top Layer w0.152: v1(77.045,22.573) J1.99@77.045,23.905
  Bottom Layer w0.152: JP1B.21@76,2 75.015,2.985 75.015,5.617 77.045,7.647 v1(77.045,22.573)
J1_100: J1.100 JP1B.22 | length 14.2
  Top Layer w0.152: JP1B.22@76,4 77.045,5.045 J1.100@77.045,17.725
J1_103: J1.103 JP1B.23 | length 25.3
  Top Layer w0.152: J1.103@78.045,23.905 v1(78.045,25.206)
  Bottom Layer w0.152: v1@77.999,25.16 77.999,6.569 77.015,5.585 77.015,2.985 JP1B.23@78,2
J1_104: J1.104 JP1B.24 | length 13.7
  Top Layer w0.152: JP1B.24@78,4 78.045,4.045 J1.104@78.045,17.725
J1_105: J1.105 JP1B.25 | length 22.5
  Top Layer w0.152: v1(78.545,22.573) J1.105@78.545,23.905
  Bottom Layer w0.152: v1(78.545,22.573) 78.545,6.167 79.015,5.697 79.015,2.985 JP1B.25@80,2
J1_106: J1.106 JP1B.26 | length 14.3
  Top Layer w0.152: J1.106@78.545,17.725 78.545,5.455 JP1B.26@80,4
J1_109: J1.109 JP1B.27 | length 25.5
  Top Layer w0.152: J1.109@79.545,23.905 v1(79.545,25.206)
  Bottom Layer w0.152: v1@79.499,25.16 79.499,7.339 81.015,5.823 81.015,2.985 JP1B.27@82,2
J1_110: J1.110 JP1B.28 | length 14.7
  Top Layer w0.152: J1.110@79.545,17.725 79.545,6.455 JP1B.28@82,4
J1_111: J1.111 JP1B.29 | length 23.5
  Top Layer w0.152: v1(80.045,22.573) J1.111@80.045,23.905
  Bottom Layer w0.152: v1(80.045,22.573) 80.045,8.825 83.015,5.855 83.015,2.985 JP1B.29@84,2
J1_112: J1.112 JP1B.30 | length 15.4
  Top Layer w0.152: J1.112@80.045,17.725 80.045,7.955 JP1B.30@84,4
J1_115: J1.115 JP1B.31 | length 26.6
  Top Layer w0.152: J1.115@81.045,23.905 v1(81.045,25.206)
  Bottom Layer w0.152: v1(81.045,25.206) 80.999,25.16 80.999,9.649 85.015,5.633 85.015,2.985 JP1B.31@86,2
J1_116: J1.116 JP1B.32 | length 15.8
  Top Layer w0.152: J1.116@81.045,17.725 81.045,8.955 JP1B.32@86,4
J1_117: J1.117 JP1B.33 | length 24.6
  Top Layer w0.152: v1(81.545,22.573) J1.117@81.545,23.905
  Bottom Layer w0.152: v1(81.545,22.573) 81.545,11.135 87.015,5.665 87.015,2.985 JP1B.33@88,2
J1_118: J1.118 JP1B.34 | length 16.4
  Top Layer w0.152: J1.118@81.545,17.725 81.545,10.455 JP1B.34@88,4
J1_121: J1.121 JP1B.35 | length 25.6
  Top Layer w0.152: J1.121@87.545,23.905 v1(87.545,25.206)
  Bottom Layer w0.152: v1(87.545,25.206) 87.499,25.16 87.499,7.213 89.015,5.697 89.015,2.985 JP1B.35@90,2
J1_122: J1.122 JP1B.36 | length 14.7
  Top Layer w0.152: J1.122@87.545,17.725 87.545,10.543 90,8.088 JP1B.36@90,4
J1_123: J1.123 JP1B.37 | length 23.5
  Top Layer w0.152: v1(88.045,22.573) J1.123@88.045,23.905
  Bottom Layer w0.152: v1(88.045,22.573) 88.045,8.699 91.021,5.723 91.021,2.979 JP1B.37@92,2
J1_124: J1.124 JP1B.38 | length 15.4
  Top Layer w0.152: J1.124@88.045,17.725 88.045,10.805 92,6.85 JP1B.38@92,4
J1_127: J1.127 JP1C.3 | length 31.6
  Top Layer w0.152: J1.127@89.045,23.905 v1(89.045,25.206)
  Bottom Layer w0.152: v1(89.045,25.206) 88.999,25.16 88.999,21.207 105.017,5.189 105.017,2.983 JP1C.3@106,2
J1_128: J1.128 JP1C.4 | length 26.5
  Top Layer w0.152: J1.128@89.045,17.725 89.045,11.075 94.586,5.534 104.466,5.534 JP1C.4@106,4
J1_129: J1.129 JP1C.5 | length 30.4
  Top Layer w0.152: v1(89.545,22.573) J1.129@89.545,23.905
  Bottom Layer w0.152: v1(89.545,22.573) 89.545,21.423 104.102,6.866 105.626,6.866 106.998,5.494 106.998,3.002 JP1C.5@108,2
J1_130: J1.130 JP1C.6 | length 27.9
  Top Layer w0.152: J1.130@89.545,17.725 89.545,11.337 94.84,6.042 105.958,6.042 JP1C.6@108,4
J1_133: J1.133 JP1C.7 | length 34.2
  Top Layer w0.152: J1.133@90.545,23.905 v1(90.545,25.206)
  Bottom Layer w0.152: v1(90.545,25.206) 90.499,25.16 90.499,21.231 104.204,7.526 106.998,7.526 109.004,5.52 109.004,2.996 JP1C.7@110,2
J1_134: J1.134 JP1C.8 | length 28.9
  Top Layer w0.152: J1.134@90.545,17.725 90.545,11.353 95.094,6.804 107.196,6.804 JP1C.8@110,4
J1_135: J1.135 JP1C.9 | length 33
  Top Layer w0.152: v1(91.045,22.573) J1.135@91.045,23.905
  Bottom Layer w0.152: v1(91.045,22.573) 91.045,21.447 104.102,8.39 108.166,8.39 111.036,5.52 111.036,2.964 JP1C.9@112,2
J1_136: J1.136 JP1C.10 | length 30.2
  Top Layer w0.152: J1.136@91.045,17.725 91.045,11.615 95.348,7.312 108.688,7.312 JP1C.10@112,4
J1_139: J1.139 JP1C.11 | length 36.8
  Top Layer w0.152: J1.139@92.045,23.905 v1(92.045,25.206)
  Bottom Layer w0.152: v1(92.045,25.206) 91.999,25.16 91.999,21.255 104.305,8.949 109.639,8.949 113.043,5.545 113.043,2.957 JP1C.11@114,2
J1_140: J1.140 JP1C.12 | length 31.2
  Top Layer w0.152: J1.140@92.045,17.725 92.045,11.631 95.602,8.074 109.926,8.074 JP1C.12@114,4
